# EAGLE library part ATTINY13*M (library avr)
MICROCONTROLLER 1 Kbytes FLASH 64 bytes EEPROM 64 bytes RAM 4-channel 10 bit ADC
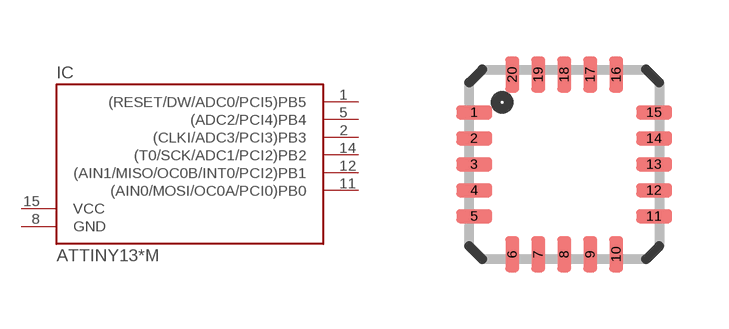
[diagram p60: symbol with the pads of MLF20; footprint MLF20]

Designator prefix IC

## ATTINY13-20M, ATTINY13V-10M  [MLF20]
1  (RESET/DW/ADC0/PCI5)PB5
2  (CLKI/ADC3/PCI3)PB3
3  P$1  nc
4  P$2  nc
5  (ADC2/PCI4)PB4
6  P$3  nc
7  P$4  nc
8  GND  pwr
9  P$5  nc
10  P$6  nc
11  (AIN0/MOSI/OC0A/PCI0)PB0
12  (AIN1/MISO/OC0B/INT0/PCI2)PB1
13  P$7  nc
14  (T0/SCK/ADC1/PCI2)PB2
15  VCC  pwr
16  P$8  nc
17  P$9  nc
18  P$10  nc
19  P$11  nc
20  P$12  nc

## Footprint MLF20 (pad centres in mm)
HP-VFQFP-N20 Micro Lead Frame package (MLF)
smd 0.9 x 0.35: 1 -2.25,1.3; 2 -2.25,0.65; 3 -2.25,0; 4 -2.25,-0.65; 5 -2.25,-1.3; 11 2.25,-1.3; 12 2.25,-0.65; 13 2.25,0; 14 2.25,0.65; 15 2.25,1.3
smd 0.35 x 0.9: 6 -1.3,-2.25; 7 -0.65,-2.25; 8 0,-2.25; 9 0.65,-2.25; 10 1.3,-2.25; 16 1.3,2.25; 17 0.65,2.25; 18 0,2.25; 19 -0.65,2.25; 20 -1.3,2.25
